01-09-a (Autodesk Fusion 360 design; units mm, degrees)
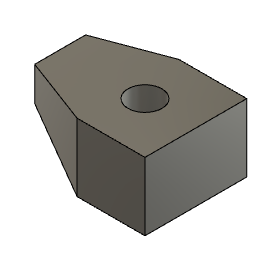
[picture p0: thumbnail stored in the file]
sketch "スケッチ1" plane through (0, 0, 0) normal (0, 0, 1) x axis (1, 0, 0)
  line L1 (-40, 0) -> (0, 0)
  line L2 (-40, 20) -> (-40, 0)
  line L3 (0, 20) -> (-40, 20)
  line L4 (0, 0) -> (0, 20)
  point P1 (0, 0)
  point P2 (0, 0)
  point P5 (0, 20)
  point P4 (-40, 20)
  horizontal L1
  vertical L2
  horizontal L3
  vertical L4
  coincident P1 P2
  dimension "d1" distance P2 P5 = 20
  dimension "d2" distance P4 P5 = 40
extrude "押し出し1" new body sketch "スケッチ1" distance 30
sketch "スケッチ2" plane through (0, 20, 0) normal (0, 1, 0) x axis (-1, 0, 0)
  line L1 (40, 15) -> (40, -15)
  line L2 (0, 15) -> (40, 15)
  line L3 (0, -15) -> (0, 15)
  line L4 (40, -15) -> (0, -15)
  line L5 (0, -15) -> (20, -15)
  line L6 (0, 15) -> (0, -15)
  line L7 (40, -7.5) -> (40, 7.5)
  line L8 (20, -15) -> (40, -7.5)
  line L9 (20, 15) -> (0, 15)
  line L10 (40, 7.5) -> (20, 15)
  point P6 (20, -15)
  point P7 (0, -15)
  point P9 (40, 7.5)
  point P10 (40, -7.5)
  parallel L4 L5
  perpendicular L4 L6
  perpendicular L2 L7
  perpendicular L6 L9
  equal L8 L10
  equal L5 L9
  collinear L4 L5
  collinear L3 L6
  collinear L2 L9
  collinear L1 L7
  dimension "d5" distance P6 P7 = 20
  dimension "d6" distance P9 P10 = 15
extrude "押し出し2" sketch "スケッチ2" no distance stored
sketch "スケッチ3" plane through (0, 0, 0) normal (0, 0, 1) x axis (1, 0, 0)
  line L1 (-20, 0) -> (-40, 10)
  line L2 (-40, 0) -> (-20, 0)
  line L3 (-40, 10) -> (-40, 0)
  line L4 (-20, 0) -> (-40, 0)
  line L5 (-40, 0) -> (-40, 20)
  line L6 (-40, 20) -> (-20, 20)
  line L7 (0, 20) -> (0, 0)
  point P2 (-40, 10)
  point P3 (-20, 0)
  horizontal L2
  collinear L2 L4
  collinear L3 L5
  dimension "d8" distance P2 L6 = 10
  dimension "d9" distance P3 L7 = 20
extrude "押し出し3" cut sketch "スケッチ3" profile of L1 L2 L3 L4 L5 no distance stored
sketch "スケッチ4" plane through (0, 20, 0) normal (0, 1, 0) x axis (-1, 0, 0)
  line L1 (40, -7.5) -> (20, -15)
  line L2 (40, 7.5) -> (40, -7.5)
  line L3 (20, 15) -> (40, 7.5)
  line L4 (0, 15) -> (20, 15)
  line L5 (0, -15) -> (0, 15)
  line L6 (20, -15) -> (0, -15)
  circle C1 centre (15, 0) radius 5
  point P1 (0, 0)
  point P8 (15, 0)
  horizontal P1 P8
  dimension "d11" distance L5 P8 = 15
  dimension "d12" diameter C1 = 10
extrude "押し出し4" cut sketch "スケッチ4" profile of C1 no distance stored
